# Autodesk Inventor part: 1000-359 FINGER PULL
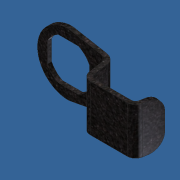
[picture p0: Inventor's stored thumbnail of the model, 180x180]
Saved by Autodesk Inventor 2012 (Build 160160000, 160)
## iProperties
Created: 2007-03
Part Number: 1000-359 FINGER PULL
Document SubType Name: Modeling
Designer: Andy Moles
Material: Steel
Mass: 23.5124 g
Surface Area: 35.2252 cm^2
Volume: 2.99522 cm^3
Density: 7.85 g/cm^3
Translation Standard: STEP AP203
File Name: 1000-359_PRT
Preprocessor: PRO/ENGINEER BY PARAMETRIC TECHNOLOGY CORPORATION, 2001390
Postprocessor: Build: 344b, Release: 11 SP2 - Date: Fri 08/18/2006
Sent Units: MILLIMETERS
Uncertainty: 0.007209068323802
Author: Andy Moles
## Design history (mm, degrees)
feature "Base1"
body "Solid1"
